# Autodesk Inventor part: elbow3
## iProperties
Shininess: 64.0
Length Units: 11269
Angle Units: 11279
Time Units: 11290
Mass Units: 11283
Length Display Precision: 3
Angle Display Precision: 2
Compacted: True
Part Number: elbow3
Document SubType Name: Modeling
Created: 2003-07
Designer: JB
Density: 0.0
Volumn: 0.0
Area: 0.0
PropertySet Name: Model Information
Control State: 0
Master: False
Checked Out: False
Author: JB
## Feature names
1. Sweep2
